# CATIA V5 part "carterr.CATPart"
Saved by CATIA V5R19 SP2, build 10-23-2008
Part number: carter
Bounding box of the stored display mesh (mm): x 0 to 220, y 0 to 140, z 0 to 300
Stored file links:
  G:\EU_thinkMotion\CFAO_2010\MMS_groupe2\MMS_groupe2\OK\mayache\mayache\pièces\carterr.CATPart
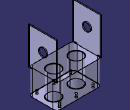
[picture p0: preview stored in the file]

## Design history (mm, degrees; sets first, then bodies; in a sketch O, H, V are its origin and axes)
Parameters
  longcarter = 220 mm
  largcarter = 140 mm
  hautcarter = 120 mm
  raypiston = 30 mm
  raypion = 5 mm
  raytrouvilb = 20 mm
  hauttrouvilb = 95 mm
  positalesage = 55 mm
Body1 (main body)
  Sketch1 on xy-plane, origin (0, 0, 0), H (1, 0, 0), V (0, 1, 0)
    line L1 (0, 0) -> (0, 140)
    line L2 (0, 140) -> (220, 140)
    line L3 (220, 140) -> (220, 0)
    point P3 (220, 0)
    line L4 (220, 0) -> (0, 0)
    length L4 = 220 {= longcarter}
    length L1 = 140 {= largcarter}
    vertical: L1 V, L3 V
    horizontal: L2 H, L4 H
    coincidence: P3 H
  Pad1: profile Sketch1, direction (0, 0, 1), length 120 {= hautcarter}
  Body2
    Sketch2 on end face of Pad1, origin (0, 0, 120), H (1, 0, 0), V (0, 1, 0)
      circle A1 centre (55, 70) radius 30
      point P1 (55, 70)
      reference projected line E1 (220, 140) -> (0, 140) from edge [face of Pad1 from Sketch1.L2 | end face of Pad1]
      reference projected line E2 (0, 140) -> (0, 0) from edge [face of Pad1 from Sketch1.L1 | end face of Pad1]
      circle A2 centre (165, 70) radius 30
      point P2 (165, 70)
      reference projected line E3 (220, 140) -> (0, 140) from edge [face of Pad1 from Sketch1.L2 | end face of Pad1]
      reference projected line E4 (220, 0) -> (220, 140) from edge [face of Pad1 from Sketch1.L3 | end face of Pad1]
      radius A1 = 30 {= raypiston}
      distance P1 E1 = 70 {= largcarter /2}
      distance P1 E2 = 55 {= positalesage}
      radius A2 = 30 {= raypiston}
      distance P2 E3 = 70 {= largcarter /2}
      distance P2 E4 = 55 {= positalesage}
    Pad2: profile Sketch2, direction (0, 0, -1), length 500
  Remove1: tool Body2
  Chamfer1: length 2, angle 45, on edge [face of Pad2 from Sketch2.A2 | start face of Pad1]
  Chamfer2: length 2, angle 45, on edge [end face of Pad1 | face of Pad2 from Sketch2.A2]
  Chamfer3: length 2, angle 45, on edge [end face of Pad1 | face of Pad2 from Sketch2.A1]
  Fillet1: radius 20, on edge [face of Pad1 from Sketch1.L1 | face of Pad1 from Sketch1.L2]
  Fillet2: radius 20, on edge [face of Pad1 from Sketch1.L2 | face of Pad1 from Sketch1.L3]
  Fillet3: radius 20, on edge [face of Pad1 from Sketch1.L4 | face of Pad1 from Sketch1.L1]
  Fillet4: radius 20, on edge [face of Pad1 from Sketch1.L3 | face of Pad1 from Sketch1.L4]
  Chamfer4: length 2, angle 45, on edge [face of Pad2 from Sketch2.A1 | start face of Pad1]
  Sketch3 on start face of Pad1, origin (0, 0, 0), H (1, 0, 0), V (0, -1, 0)
    circle A1 centre (27.5, -125) radius 5
    point P1 (27.5, -125)
    circle A2 centre (110, -125) radius 5
    point P2 (110, -125)
    circle A3 centre (192.5, -125) radius 5
    point P3 (192.5, -125)
    reference projected line E1 (220, -140) -> (0, -140) from edge [start face of Pad1 | face of Pad1 from Sketch1.L2]
    reference projected line E2 (220, -140) -> (0, -140) from edge [start face of Pad1 | face of Pad1 from Sketch1.L2]
    reference projected line E3 (220, -140) -> (0, -140) from edge [start face of Pad1 | face of Pad1 from Sketch1.L2]
    reference projected line E4 (0, -140) -> (0, 0) from edge [start face of Pad1 | face of Pad1 from Sketch1.L1]
    reference projected line E5 (220, 0) -> (220, -140) from edge [start face of Pad1 | face of Pad1 from Sketch1.L3]
    reference projected line E6 (0, -140) -> (0, 0) from edge [start face of Pad1 | face of Pad1 from Sketch1.L1]
    radius A3 = 5 {= raypion}
    radius A2 = 5 {= raypion}
    radius A1 = 5 {= raypion}
    distance P1 E1 = 15
    distance P2 E2 = 15
    distance P3 E3 = 15
    distance P1 E4 = 27.5 {= longcarter /8}
    distance P3 E5 = 27.5 {= longcarter /8}
    distance P2 E6 = 110 {= longcarter /2}
  Pocket1: profile Sketch3, direction (0, 0, 1), length 15
  Sketch4 on start face of Pad1, origin (0, 0, 0), H (1, 0, 0), V (0, -1, 0)
    circle A1 centre (27.5, -15) radius 5
    point P1 (27.5, -15)
    circle A2 centre (110, -15) radius 5
    point P2 (110, -15)
    circle A3 centre (192.5, -15) radius 5
    point P3 (192.5, -15)
    reference projected line E1 (0, -140) -> (0, 0) from edge [start face of Pad1 | face of Pad1 from Sketch1.L1]
    reference projected line E2 (0, 0) -> (220, 0) from edge [start face of Pad1 | face of Pad1 from Sketch1.L4]
    reference projected line E3 (0, 0) -> (220, 0) from edge [start face of Pad1 | face of Pad1 from Sketch1.L4]
    reference projected line E4 (0, -140) -> (0, 0) from edge [start face of Pad1 | face of Pad1 from Sketch1.L1]
    reference projected line E5 (0, 0) -> (220, 0) from edge [start face of Pad1 | face of Pad1 from Sketch1.L4]
    reference projected line E6 (220, 0) -> (220, -140) from edge [start face of Pad1 | face of Pad1 from Sketch1.L3]
    radius A3 = 5 {= raypion}
    radius A2 = 5 {= raypion}
    radius A1 = 5 {= raypion}
    distance P1 E1 = 27.5 {= longcarter /8}
    distance P1 E2 = 15
    distance P2 E3 = 15
    distance P2 E4 = 110 {= longcarter /2}
    distance P3 E5 = 15
    distance P3 E6 = 27.5 {= longcarter /8}
  Pocket2: profile Sketch4, direction (0, 0, 1), length 15
  Chamfer5: length 1, angle 45, on edge [start face of Pad1 | face of Pad1 from Sketch1.L1]
  Plane1: type Offset, RefPlane face of Pad1 from Sketch1.L1, Offset 110 {= longcarter /2}
  Plane2: type Offset, RefPlane start face of Pad1, Offset 60 {= hautcarter /2}
  Plane3: type Offset, RefPlane face of Pad1 from Sketch1.L2, Offset 70 {= largcarter /2}
  Body3
    Sketch5 on end face of Pad1, origin (0, 0, 120), H (1, 0, 0), V (0, 1, 0)
      line L1 (0, 0) -> (0, 140)
      line L2 (0, 140) -> (5, 140)
      line L3 (5, 140) -> (5, 0)
      point P3 (5, 0)
      line L4 (5, 0) -> (0, 0)
      length L1 = 140 {= largcarter}
      distance L1 L3 = 5
      vertical: L1 V, L3 V
      horizontal: L2 H, L4 H
      coincidence: P3 H
    Pad3: profile Sketch5, direction (0, 0, 1), length 180 {= hautcarter*1.5}
    Fillet5: radius 2, on edge [face of Pad3 from Sketch5.L2 | face of Pad3 from Sketch5.L3]; edge [face of Pad3 from Sketch5.L1 | face of Pad3 from Sketch5.L2]; edge [face of Pad3 from Sketch5.L4 | face of Pad3 from Sketch5.L1]; edge [face of Pad3 from Sketch5.L3 | face of Pad3 from Sketch5.L4]
    Mirror1: of Pad3, about Plane1
    Fillet6: radius 2, on edge [face of Mirror1 | face of Mirror1] (x4)
    Body4
      Sketch6 on face of Mirror1, origin (220, 0, 0), H (0, 1, 0), V (0, 0, 1)
        circle A1 centre (70, 215) radius 20
        point P1 (70, 215)
        reference projected line E1 (140, 120) -> (0, 120) from edge [face of Mirror1 | face of Mirror1]
        reference projected line E2 (140, 150) -> (140, 300) from edge [face of Mirror1 | face of Fillet6]
        radius A1 = 20 {= raytrouvilb}
        distance P1 E1 = 95 {= hauttrouvilb}
        distance E2 P1 = 70 {= largcarter /2}
      Pad4: profile Sketch6, direction (1, 0, 0), length 600, mirrored extent
    Remove2: tool Body4
  Assemble1: tool Body3
Relations
  Sketch3.distance(P1 E4) = =longcarter /8 (deactivated)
